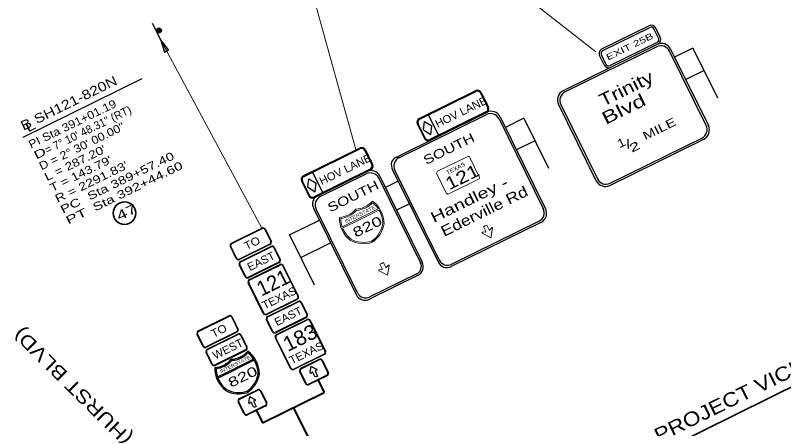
# Model space of a CAD drawing. Extents: x 2356431 to 2371438, y 6972864 to 6982525.
# Drawn here: x 2366973 to 2368116, y 6979508 to 6980123 of the extents above; entities that cross this region are included whole.
import ezdxf
from ezdxf.enums import TextEntityAlignment as Align

# ---------------------------------------------------------------- set-up
doc = ezdxf.new("R2010")
doc.units = 0
doc.header["$LTSCALE"] = 5.6
for name, color, linetype, lineweight in [('1', 7, 'Continuous', 25), ('13', 7, 'Continuous', 13), ('17', 7, 'Continuous', 35), ('28', 7, 'Continuous', 35), ('48', 7, 'Continuous', 25), ('53', 7, 'Continuous', 13), ('61', 7, 'Continuous', 13)]:
    doc.layers.add(name, color=color, linetype=linetype, lineweight=lineweight)
doc.layers.add('33', color=7, linetype='Continuous')

msp = doc.modelspace()

# ---------------------------------------------------------------- hatches: boundary and pattern name
at = {"layer": '1'}
for points in [[(2367190.135, 6980100.144, 1), (2367182.759, 6980101.279, 1)], [(2367188.543, 6980086.99), (2367194.613, 6980068.425), (2367200.923, 6980071.868)]]:
    msp.add_hatch(color=256, dxfattribs=at).paths.add_polyline_path(points)

# ---------------------------------------------------------------- linework, layer by layer
at = {"layer": '1', "lineweight": 13}
for p, q in [((2367297.678, 6980492.815), (2367836.822, 6980068.714)), ((2367347.891, 6980400.061), (2367480.094, 6979921.582)), ((2367188.543, 6980086.99), (2367339.735, 6979806.183)), ((2367645.503, 6979912.706), (2367601.335, 6979890.923)), ((2367663.388, 6979882.78), (2367649.264, 6979911.424)), ((2367600.061, 6979887.155), (2367614.185, 6979858.509)), ((2367617.952, 6979857.236), (2367662.114, 6979879.013)), ((2367512.971, 6979834.789), (2367486.067, 6979821.516)), ((2367513.98, 6979833.174), (2367486.906, 6979819.821)), ((2367459.166, 6979808.243), (2367486.067, 6979821.516)), ((2367459.816, 6979806.452), (2367486.906, 6979819.821))]:
    msp.add_line(p, q, dxfattribs=at)
at = {"layer": '1'}
for p, q in [((2367176.471, 6980111.555), (2367188.543, 6980086.99)), ((2367845.939, 6980073.212), (2367915.89, 6980107.721)), ((2367847.18, 6980070.694), (2367917.139, 6980105.194)), ((2367930.246, 6980089.228), (2367923.418, 6980103.068)), ((2367932.767, 6980090.469), (2367925.944, 6980104.312)), ((2367929.364, 6980080.427), (2367788.124, 6980010.762)), ((2367927.599, 6980076.421), (2367791.057, 6980009.062)), ((2367928.112, 6980082.955), (2367858.154, 6980048.442)), ((2368001.048, 6979959.323), (2367946.431, 6980070.028)), ((2367948.121, 6980072.954), (2368004.4, 6979958.885)), ((2367981.43, 6980074.563), (2367954.002, 6980061.034)), ((2367981.429, 6980074.563), (2368018.097, 6980000.231)), ((2367849.355, 6980049.329), (2367842.524, 6980063.166)), ((2367851.874, 6980050.573), (2367845.052, 6980064.412)), ((2367998.02, 6980040.932), (2367970.594, 6980027.403)), ((2367837.583, 6979876.599), (2367781.31, 6979990.67)), ((2367784.666, 6979990.232), (2367839.277, 6979879.526)), ((2367539.082, 6979911.593), (2367674.314, 6979978.71)), ((2367543.756, 6979911.193), (2367673.876, 6979975.358)), ((2367692.71, 6979968.968), (2367758.66, 6979835.274)), ((2367694.403, 6979971.894), (2367762.01, 6979834.836)), ((2367729.618, 6979969.859), (2367702.19, 6979956.329)), ((2367729.617, 6979969.859), (2367766.285, 6979895.526)), ((2367858.104, 6979873.136), (2367994.652, 6979940.489)), ((2367746.208, 6979936.228), (2367718.782, 6979922.698)), ((2367857.668, 6979869.784), (2367997.577, 6979938.796)), ((2367421.791, 6979853.716), (2367497.439, 6979891.235)), ((2367426.465, 6979853.317), (2367494.798, 6979887.021)), ((2367515.32, 6979883.546), (2367578.396, 6979755.665)), ((2367534.333, 6979892.951), (2367601.929, 6979755.895)), ((2367603.622, 6979758.821), (2367537.67, 6979892.519)), ((2367513.639, 6979880.62), (2367575.88, 6979754.423)), ((2367542.653, 6979876.079), (2367523.63, 6979866.697)), ((2367559.24, 6979842.445), (2367540.22, 6979833.063)), ((2367417.041, 6979835.073), (2367480.12, 6979707.171)), ((2367481.811, 6979710.097), (2367420.38, 6979834.643)), ((2367381.034, 6979796.36), (2367425.353, 6979818.222)), ((2367755.195, 6979814.747), (2367621.738, 6979748.944)), ((2367752.269, 6979816.442), (2367622.456, 6979752.43)), ((2367381.034, 6979796.36), (2367417.7, 6979722.026)), ((2367397.623, 6979762.729), (2367441.94, 6979784.587)), ((2367571.578, 6979735.577), (2367499.926, 6979700.232)), ((2367570.576, 6979738.213), (2367500.644, 6979703.719)), ((2367327.43, 6979611.196), (2367300.529, 6979597.916)), ((2367328.437, 6979609.582), (2367301.368, 6979596.223)), ((2367273.629, 6979584.639), (2367300.529, 6979597.916)), ((2367274.279, 6979582.85), (2367301.368, 6979596.223))]:
    msp.add_line(p, q, dxfattribs=at)
msp.add_lwpolyline([(2367188.543, 6980086.99), (2367194.613, 6980068.425), (2367200.923, 6980071.868)], close=True, dxfattribs=at)
msp.add_circle((2367186.447, 6980100.712), 3.732, dxfattribs=at)
for centre, radius, start, end in [((2367919.211, 6980101.011), 7.501, 26.25603, 116.25603), ((2367919.211, 6980101.011), 4.688, 26.25603, 116.25603), ((2367926.047, 6980087.154), 4.688, 296.25603, 26.25603), ((2367926.047, 6980087.154), 7.501, 296.25603, 26.25603), ((2367933.829, 6980063.807), 14.063, 26.25603, 116.25603), ((2367934.681, 6980066.318), 15.001, 26.25603, 116.25603), ((2367849.253, 6980066.502), 7.501, 116.25603, 206.25603), ((2367849.253, 6980066.502), 4.688, 116.25603, 206.25603), ((2367856.088, 6980052.645), 7.501, 206.25603, 296.25603), ((2367856.088, 6980052.645), 4.688, 206.25603, 296.25603), ((2367794.77, 6979997.304), 15.001, 116.25603, 206.25603), ((2367797.281, 6979996.452), 14.063, 116.25603, 206.25603), ((2367680.098, 6979962.747), 14.063, 26.25695, 116.25695), ((2367680.95, 6979965.258), 15.001, 26.25695, 116.25695), ((2367988.436, 6979953.103), 14.063, 296.25603, 26.25603), ((2367990.948, 6979952.251), 15.001, 296.25603, 26.25603), ((2367550.285, 6979898.737), 14.063, 116.25695, 206.25695), ((2367501.027, 6979874.396), 14.063, 26.25695, 116.25695), ((2367501.879, 6979876.907), 15.001, 26.25695, 116.25695), ((2367851.037, 6979883.236), 15.001, 206.25603, 296.25603), ((2367851.889, 6979885.747), 14.063, 206.25603, 296.25603), ((2367432.993, 6979840.86), 14.063, 116.25695, 206.25695), ((2367746.048, 6979829.053), 14.063, 296.25695, 26.25695), ((2367748.56, 6979828.201), 15.001, 296.25695, 26.25695), ((2367678.47, 6979804.117), 0.506, 206.25516, 316.23827), ((2367672.476, 6979801.161), 0.506, 276.27206, 26.25516), ((2367616.235, 6979765.042), 14.063, 206.25695, 296.25695), ((2367518.505, 6979745.223), 0.506, 276.27206, 26.25516), ((2367524.498, 6979748.179), 0.506, 206.25516, 316.23827), ((2367564.944, 6979749.029), 12.195, 296.25606, 26.25398), ((2367564.944, 6979749.029), 15, 296.25606, 26.25398), ((2367615.383, 6979762.531), 15.001, 206.25695, 296.25695), ((2367493.571, 6979713.819), 15.001, 206.25695, 296.25695), ((2367494.423, 6979716.33), 14.063, 206.25695, 296.25695), ((2367291.938, 6979646.838), 35.984, 273.44817, 318.29849), ((2367291.938, 6979646.838), 37.874, 274.64609, 315.64292), ((2367294.046, 6979589.03), 41.954, 0.13097, 53.83335), ((2367294.046, 6979589.03), 40.064, 33.57742, 51.44217), ((2367266.909, 6979634.485), 35.984, 274.23709, 319.0874), ((2367266.909, 6979634.485), 37.874, 276.89265, 317.88949), ((2367294.046, 6979589.03), 40.064, 0.34751, 30.85949), ((2367311.511, 6979597.649), 41.954, 178.70222, 232.4046), ((2367311.511, 6979597.649), 40.064, 181.0934, 198.95816), ((2367295.806, 6979595.51), 38.808, 304.10583, 350.75221), ((2367295.806, 6979595.51), 40.698, 303.73968, 350.97558), ((2367311.511, 6979597.649), 40.064, 201.67608, 232.18806), ((2367305.297, 6979600.194), 40.698, 241.55999, 288.79589), ((2367305.297, 6979600.194), 38.808, 241.78337, 288.42975)]:
    msp.add_arc(centre, radius, start, end, dxfattribs=at)
at = {"layer": '1', "lineweight": 13}
for centre, radius, start, end in [((2367646.743, 6979910.179), 2.813, 26.25588, 116.25588), ((2367602.583, 6979888.396), 2.813, 116.25588, 206.25588), ((2367660.869, 6979881.541), 2.813, 296.25588, 26.25588), ((2367616.71, 6979859.758), 2.813, 206.25588, 296.25588), ((2367477.488, 6979870.438), 35.984, 273.43645, 318.28676), ((2367477.488, 6979870.438), 37.874, 274.63436, 315.6312), ((2367479.584, 6979812.63), 41.954, 0.11925, 53.82162), ((2367479.584, 6979812.63), 40.064, 33.56569, 51.43044), ((2367452.456, 6979858.091), 35.984, 274.22536, 319.07567), ((2367452.456, 6979858.091), 37.874, 276.88092, 317.87776), ((2367479.584, 6979812.63), 40.064, 0.33578, 30.84777), ((2367497.05, 6979821.246), 41.954, 178.6905, 232.39288), ((2367497.05, 6979821.246), 40.064, 181.08168, 198.94643), ((2367497.05, 6979821.246), 40.064, 201.66436, 232.17634), ((2367481.345, 6979819.109), 38.808, 304.0941, 350.74048), ((2367481.345, 6979819.109), 40.698, 303.72796, 350.96386), ((2367490.838, 6979823.791), 40.698, 241.54826, 288.78416), ((2367490.838, 6979823.791), 38.808, 241.77164, 288.41802)]:
    msp.add_arc(centre, radius, start, end, dxfattribs=at)
at = {"layer": '1'}
for centre in [(2367546.174, 6979898.277), (2367428.883, 6979840.401)]:
    msp.add_ellipse(centre, major_axis=(-9.412, 11.91), ratio=0.848877, start_param=6.07270093, end_param=7.64349725, dxfattribs=at)
at = {"layer": '17'}
msp.add_line((2367561.881, 6979290.19), (2368209.441, 6979609.782), dxfattribs=at)
msp.add_circle((2367135.069, 6979828.531), 16.828, dxfattribs=at)
at = {"layer": '48'}
for p, q in [((2367573.76, 6979969.338), (2367658.355, 6980011.063)), ((2367574.911, 6979968.677), (2367658.176, 6980009.753)), ((2367666.266, 6980008.381), (2367676.999, 6979986.622)), ((2367675.681, 6979986.796), (2367665.6, 6980007.232)), ((2367587.464, 6979974.869), (2367602.447, 6979944.493)), ((2367674.314, 6979978.71), (2367589.721, 6979936.978)), ((2367673.158, 6979979.376), (2367589.893, 6979938.3)), ((2367580.483, 6979952.441), (2367581.921, 6979965.109)), ((2367581.921, 6979965.109), (2367592.848, 6979958.541)), ((2367571.076, 6979961.426), (2367581.868, 6979939.548)), ((2367572.397, 6979961.253), (2367582.476, 6979940.816)), ((2367580.483, 6979952.441), (2367591.411, 6979945.874)), ((2367591.411, 6979945.874), (2367592.848, 6979958.541)), ((2367401.358, 6979883.971), (2367485.954, 6979925.695)), ((2367402.507, 6979883.308), (2367485.773, 6979924.383)), ((2367503.279, 6979901.427), (2367493.198, 6979921.863)), ((2367493.864, 6979923.012), (2367504.597, 6979901.253)), ((2367500.756, 6979894.007), (2367417.49, 6979852.932)), ((2367415.061, 6979889.501), (2367430.045, 6979859.125)), ((2367501.911, 6979893.342), (2367417.319, 6979851.609)), ((2367398.674, 6979876.058), (2367409.466, 6979854.179)), ((2367399.995, 6979875.884), (2367410.074, 6979855.447)), ((2367408.082, 6979867.073), (2367409.52, 6979879.74)), ((2367409.52, 6979879.74), (2367420.447, 6979873.173)), ((2367419.009, 6979860.505), (2367420.447, 6979873.173)), ((2367408.082, 6979867.073), (2367419.009, 6979860.505)), ((2367294.5, 6979783.858), (2367339.735, 6979806.183)), ((2367294.839, 6979783.169), (2367340.074, 6979805.494)), ((2367344.189, 6979804.099), (2367352.825, 6979786.6)), ((2367344.877, 6979804.439), (2367353.514, 6979786.94)), ((2367302.08, 6979761.556), (2367293.444, 6979779.055)), ((2367351.43, 6979782.486), (2367306.195, 6979760.161)), ((2367351.77, 6979781.797), (2367306.535, 6979759.472)), ((2367307.862, 6979756.782), (2367353.097, 6979779.107)), ((2367301.392, 6979761.216), (2367292.756, 6979778.715)), ((2367308.202, 6979756.094), (2367353.437, 6979778.419)), ((2367357.551, 6979777.023), (2367366.188, 6979759.525)), ((2367358.24, 6979777.363), (2367366.876, 6979759.865)), ((2367314.754, 6979734.141), (2367306.118, 6979751.639)), ((2367315.443, 6979734.481), (2367306.807, 6979751.979)), ((2367364.792, 6979755.411), (2367319.557, 6979733.086)), ((2367365.132, 6979754.722), (2367319.897, 6979732.397)), ((2367321.225, 6979729.707), (2367366.46, 6979752.032)), ((2367321.565, 6979729.018), (2367366.8, 6979751.343)), ((2367370.914, 6979749.948), (2367393.239, 6979704.713)), ((2367371.603, 6979750.288), (2367393.928, 6979705.053)), ((2367341.806, 6979679.329), (2367319.481, 6979724.564)), ((2367342.495, 6979679.669), (2367320.17, 6979724.904)), ((2367391.844, 6979700.598), (2367346.609, 6979678.273)), ((2367392.184, 6979699.91), (2367346.949, 6979677.585)), ((2367348.277, 6979674.895), (2367393.512, 6979697.22)), ((2367348.616, 6979674.206), (2367393.851, 6979696.531)), ((2367397.966, 6979695.136), (2367406.602, 6979677.637)), ((2367398.655, 6979695.476), (2367407.291, 6979677.977)), ((2367245.096, 6979653.226), (2367290.331, 6979675.551)), ((2367245.436, 6979652.537), (2367290.671, 6979674.862)), ((2367294.785, 6979673.467), (2367303.421, 6979655.968)), ((2367295.474, 6979673.807), (2367304.11, 6979656.308)), ((2367355.169, 6979652.253), (2367346.533, 6979669.752)), ((2367355.857, 6979652.593), (2367347.221, 6979670.092)), ((2367405.207, 6979673.523), (2367359.972, 6979651.198)), ((2367405.547, 6979672.834), (2367360.312, 6979650.509)), ((2367361.639, 6979647.819), (2367406.874, 6979670.144)), ((2367361.979, 6979647.13), (2367407.214, 6979669.455)), ((2367411.329, 6979668.06), (2367433.654, 6979622.825)), ((2367412.017, 6979668.4), (2367434.342, 6979623.165)), ((2367251.988, 6979630.584), (2367243.352, 6979648.083)), ((2367252.677, 6979630.924), (2367244.041, 6979648.423)), ((2367302.026, 6979651.854), (2367256.791, 6979629.529)), ((2367302.366, 6979651.165), (2367257.131, 6979628.84)), ((2367258.459, 6979626.15), (2367303.694, 6979648.475)), ((2367258.798, 6979625.461), (2367304.034, 6979647.786)), ((2367308.148, 6979646.391), (2367316.784, 6979628.893)), ((2367308.837, 6979646.731), (2367317.473, 6979629.233)), ((2367382.22, 6979597.441), (2367359.895, 6979642.676)), ((2367382.909, 6979597.781), (2367360.584, 6979643.016)), ((2367265.351, 6979603.509), (2367256.715, 6979621.007)), ((2367266.039, 6979603.849), (2367257.403, 6979621.347)), ((2367315.389, 6979624.778), (2367270.154, 6979602.453)), ((2367315.729, 6979624.09), (2367270.494, 6979601.765)), ((2367432.258, 6979618.711), (2367387.023, 6979596.386)), ((2367432.598, 6979618.022), (2367387.363, 6979595.697)), ((2367397.909, 6979597.556), (2367424.708, 6979610.783)), ((2367398.249, 6979596.867), (2367425.048, 6979610.094)), ((2367429.162, 6979608.699), (2367437.798, 6979591.2)), ((2367429.851, 6979609.039), (2367438.487, 6979591.54)), ((2367404.801, 6979574.915), (2367396.165, 6979592.413)), ((2367405.489, 6979575.255), (2367396.853, 6979592.753)), ((2367436.403, 6979587.086), (2367409.604, 6979573.859)), ((2367436.743, 6979586.397), (2367409.944, 6979573.171)), ((2367306.338, 6979552.363), (2367333.137, 6979565.589)), ((2367306.678, 6979551.674), (2367333.477, 6979564.901)), ((2367337.592, 6979563.505), (2367346.228, 6979546.007)), ((2367338.28, 6979563.845), (2367346.916, 6979546.347)), ((2367313.23, 6979529.722), (2367304.594, 6979547.22)), ((2367313.919, 6979530.061), (2367305.283, 6979547.56)), ((2367344.833, 6979541.893), (2367318.033, 6979528.666)), ((2367345.172, 6979541.204), (2367318.373, 6979527.978))]:
    msp.add_line(p, q, dxfattribs=at)
at = {"layer": '48', "lineweight": 40}
for p, q in [((2367423.343, 6979579.784), (2367432.444, 6979561.345)), ((2367340.873, 6979516.152), (2367432.444, 6979561.345)), ((2367331.773, 6979534.591), (2367340.873, 6979516.152)), ((2367386.658, 6979538.749), (2367411.927, 6979487.55))]:
    msp.add_line(p, q, dxfattribs=at)
at = {"layer": '48'}
for points in [[(2367411.777, 6979591.018), (2367413.231, 6979600.436), (2367421.526, 6979595.911)], [(2367421.32, 6979594.485), (2367418.8, 6979593.951), (2367422.716, 6979586.013), (2367419.091, 6979584.223), (2367415.174, 6979592.161), (2367413.04, 6979590.304)], [(2367320.206, 6979545.826), (2367321.661, 6979555.243), (2367329.956, 6979550.719)], [(2367329.751, 6979549.293), (2367327.23, 6979548.758), (2367331.147, 6979540.822), (2367327.52, 6979539.031), (2367323.604, 6979546.968), (2367321.47, 6979545.112)]]:
    msp.add_lwpolyline(points, dxfattribs=at)
for centre, radius, start, end in [((2367660.633, 6980004.777), 5.54, 26.25314, 116.25314), ((2367660.969, 6980005.766), 5.909, 26.25314, 116.25314), ((2367670.709, 6979984.344), 5.54, 296.25314, 26.25314), ((2367671.698, 6979984.008), 5.909, 296.25314, 26.25314), ((2367576.375, 6979964.04), 5.909, 116.25256, 206.25256), ((2367577.364, 6979963.704), 5.54, 116.25256, 206.25256), ((2367587.108, 6979942.278), 5.909, 206.25256, 296.25256), ((2367587.444, 6979943.267), 5.54, 206.25256, 296.25256), ((2367488.231, 6979919.408), 5.54, 26.25314, 116.25314), ((2367488.567, 6979920.397), 5.909, 26.25314, 116.25314), ((2367498.307, 6979898.975), 5.54, 296.25314, 26.25314), ((2367499.296, 6979898.639), 5.909, 296.25314, 26.25314), ((2367403.973, 6979878.671), 5.909, 116.25256, 206.25256), ((2367404.962, 6979878.335), 5.54, 116.25256, 206.25256), ((2367414.707, 6979856.909), 5.909, 206.25256, 296.25256), ((2367415.042, 6979857.898), 5.54, 206.25256, 296.25256), ((2367341.434, 6979802.739), 3.84, 26.26788, 116.26788), ((2367341.434, 6979802.739), 3.072, 26.26788, 116.26788), ((2367296.199, 6979780.414), 3.84, 116.26788, 206.26788), ((2367296.199, 6979780.414), 3.072, 116.26788, 206.26788), ((2367350.07, 6979785.241), 3.072, 296.26788, 26.26788), ((2367350.07, 6979785.241), 3.84, 296.26788, 26.26788), ((2367354.797, 6979775.664), 3.84, 26.26788, 116.26788), ((2367354.797, 6979775.664), 3.072, 26.26788, 116.26788), ((2367304.835, 6979762.916), 3.84, 206.26788, 296.26788), ((2367304.835, 6979762.916), 3.072, 206.26788, 296.26788), ((2367309.562, 6979753.339), 3.84, 116.26788, 206.26788), ((2367363.433, 6979758.165), 3.072, 296.26788, 26.26788), ((2367363.433, 6979758.165), 3.84, 296.26788, 26.26788), ((2367309.562, 6979753.339), 3.072, 116.26788, 206.26788), ((2367368.159, 6979748.588), 3.84, 26.26788, 116.26788), ((2367368.159, 6979748.588), 3.072, 26.26788, 116.26788), ((2367318.198, 6979735.84), 3.84, 206.26788, 296.26788), ((2367318.198, 6979735.84), 3.072, 206.26788, 296.26788), ((2367322.924, 6979726.263), 3.84, 116.26788, 206.26788), ((2367322.924, 6979726.263), 3.072, 116.26788, 206.26788), ((2367390.484, 6979703.353), 3.072, 296.26788, 26.26788), ((2367390.484, 6979703.353), 3.84, 296.26788, 26.26788), ((2367395.211, 6979693.776), 3.84, 26.26788, 116.26788), ((2367395.211, 6979693.776), 3.072, 26.26788, 116.26788), ((2367345.249, 6979681.028), 3.84, 206.26788, 296.26788), ((2367345.249, 6979681.028), 3.072, 206.26788, 296.26788), ((2367403.847, 6979676.278), 3.072, 296.26788, 26.26788), ((2367403.847, 6979676.278), 3.84, 296.26788, 26.26788), ((2367292.03, 6979672.107), 3.84, 26.26788, 116.26788), ((2367292.03, 6979672.107), 3.072, 26.26788, 116.26788), ((2367349.976, 6979671.451), 3.84, 116.26788, 206.26788), ((2367349.976, 6979671.451), 3.072, 116.26788, 206.26788), ((2367408.574, 6979666.701), 3.84, 26.26788, 116.26788), ((2367408.574, 6979666.701), 3.072, 26.26788, 116.26788), ((2367246.795, 6979649.782), 3.84, 116.26788, 206.26788), ((2367300.666, 6979654.609), 3.072, 296.26788, 26.26788), ((2367300.666, 6979654.609), 3.84, 296.26788, 26.26788), ((2367246.795, 6979649.782), 3.072, 116.26788, 206.26788), ((2367305.393, 6979645.032), 3.84, 26.26788, 116.26788), ((2367305.393, 6979645.032), 3.072, 26.26788, 116.26788), ((2367358.612, 6979653.953), 3.84, 206.26788, 296.26788), ((2367358.612, 6979653.953), 3.072, 206.26788, 296.26788), ((2367363.339, 6979644.376), 3.84, 116.26788, 206.26788), ((2367363.339, 6979644.376), 3.072, 116.26788, 206.26788), ((2367255.431, 6979632.284), 3.84, 206.26788, 296.26788), ((2367255.431, 6979632.284), 3.072, 206.26788, 296.26788), ((2367260.158, 6979622.707), 3.84, 116.26788, 206.26788), ((2367260.158, 6979622.707), 3.072, 116.26788, 206.26788), ((2367314.029, 6979627.533), 3.072, 296.26788, 26.26788), ((2367314.029, 6979627.533), 3.84, 296.26788, 26.26788), ((2367430.899, 6979621.465), 3.072, 296.26788, 26.26788), ((2367430.899, 6979621.465), 3.84, 296.26788, 26.26788), ((2367426.408, 6979607.339), 3.84, 26.26788, 116.26788), ((2367426.408, 6979607.339), 3.072, 26.26788, 116.26788), ((2367268.794, 6979605.208), 3.84, 206.26788, 296.26788), ((2367268.794, 6979605.208), 3.072, 206.26788, 296.26788), ((2367385.664, 6979599.14), 3.84, 206.26788, 296.26788), ((2367385.664, 6979599.14), 3.072, 206.26788, 296.26788), ((2367399.608, 6979594.113), 3.84, 116.26788, 206.26788), ((2367399.608, 6979594.113), 3.072, 116.26788, 206.26788), ((2367412.533, 6979590.893), 0.767, 171.25336, 310.98193), ((2367421.159, 6979595.237), 0.767, 281.76638, 61.40499), ((2367435.044, 6979589.841), 3.072, 296.26788, 26.26788), ((2367435.044, 6979589.841), 3.84, 296.26788, 26.26788), ((2367408.244, 6979576.614), 3.84, 206.26788, 296.26788), ((2367408.244, 6979576.614), 3.072, 206.26788, 296.26788), ((2367334.837, 6979562.146), 3.84, 26.26788, 116.26788), ((2367334.837, 6979562.146), 3.072, 26.26788, 116.26788), ((2367308.038, 6979548.919), 3.84, 116.26788, 206.26788), ((2367308.038, 6979548.919), 3.072, 116.26788, 206.26788), ((2367329.589, 6979550.043), 0.767, 281.76638, 61.40499), ((2367320.962, 6979545.7), 0.767, 171.25336, 310.98193), ((2367343.473, 6979544.647), 3.072, 296.26788, 26.26788), ((2367343.473, 6979544.647), 3.84, 296.26788, 26.26788), ((2367316.674, 6979531.421), 3.84, 206.26788, 296.26788), ((2367316.674, 6979531.421), 3.072, 206.26788, 296.26788)]:
    msp.add_arc(centre, radius, start, end, dxfattribs=at)
at = {"layer": '53'}
for p, q in [((2367674.562, 6979810.877), (2367678.002, 6979803.907)), ((2367678.841, 6979803.779), (2367681.7, 6979806.77)), ((2367668.4, 6979800.206), (2367672.531, 6979800.678)), ((2367514.428, 6979744.268), (2367518.56, 6979744.74)), ((2367520.591, 6979754.939), (2367524.031, 6979747.969)), ((2367524.869, 6979747.841), (2367527.729, 6979750.833))]:
    msp.add_line(p, q, dxfattribs=at)
for points in [[(2367682.984, 6979806.096), (2367680.768, 6979791.902), (2367668.147, 6979798.778)], [(2367672.924, 6979801.401), (2367669.473, 6979808.38), (2367672.015, 6979809.632), (2367674.562, 6979810.877)], [(2367529.013, 6979750.159), (2367526.796, 6979735.964), (2367514.176, 6979742.839)], [(2367518.954, 6979745.463), (2367515.502, 6979752.442), (2367518.045, 6979753.694), (2367520.591, 6979754.939)]]:
    msp.add_lwpolyline(points, dxfattribs=at)
for centre, start, end in [((2367682.248, 6979806.239), 350.99366, 136.37479), ((2367668.493, 6979799.455), 96.13553, 241.51667), ((2367528.276, 6979750.302), 350.99366, 136.37479), ((2367514.522, 6979743.517), 96.13553, 241.51667)]:
    msp.add_arc(centre, 0.759, start, end, dxfattribs=at)
at = {"layer": '61', "lineweight": 25}
msp.add_line((2366984.556, 6979941.91), (2367161.513, 6980029.245), dxfattribs=at)

# ---------------------------------------------------------------- texts
at = {"layer": '1'}
for s, height, rotation, width, p in [('EXIT 25B', 9.188, 26.256, 1.45, (2367889.284, 6980072.648)), ('Trinity', 18.91, 26.256, 1.25, (2367886.138, 6980005.746)), ('Blvd', 18.9, 26.256, 1.4, (2367882.502, 6979975.251)), ('MILE', 12.54, 26.256, 1.35, (2367934.186, 6979948.639)), ('SOUTH', 13.5, 26.257, 1.3, (2367621.046, 6979918.368)), ('1', 12.54, 26.256, 1.3, (2367877.512, 6979927.797)), ('/', 12.54, 26.256, 1.7, (2367887.727, 6979925.727)), ('2', 12.54, 26.256, 1.65, (2367897.214, 6979921.978)), ('SOUTH', 13.5, 26.257, 1.3, (2367478.399, 6979847.678)), ('Handley -', 15.68, 26.256, 1.4, (2367651.979, 6979841.579)), ('Ederville Rd', 15.68, 26.256, 1.25, (2367674.271, 6979824.483))]:
    msp.add_text(s, height=height, rotation=rotation, dxfattribs=dict(at, width=width)).set_placement(p, align=Align.CENTER)
for s, height, rotation, width, p in [('TEXAS', 6, 26.256, 1.15, (2367615.97, 6979885.756)), ('121', 18.75, 26.256, 1.25, (2367618.575, 6979862.458)), ('INTERSTATE', 5.198, 26.256, 1.15, (2367464.48, 6979813.566)), ('820', 14.18, 26.256, 1.45, (2367479.27, 6979792.03)), ('INTERSTATE', 5.198, 26.268, 1.15, (2367278.942, 6979589.963)), ('820', 14.18, 26.268, 1.45, (2367293.737, 6979568.428))]:
    msp.add_text(s, height=height, rotation=rotation, dxfattribs=dict(at, width=width)).set_placement(p)
at = {"layer": '13', "width": 1.25}
msp.add_text('(HURST BLVD)', height=20, rotation=135.331, dxfattribs=at).set_placement((2367148.363, 6979495.458))
at = {"layer": '17', "width": 1.5}
msp.add_text('47', height=14, rotation=26.268, dxfattribs=at).set_placement((2367141.314, 6979823.806), align=Align.CENTER)
at = {"layer": '17', "width": 1.2}
msp.add_text('PROPERTY OWNERS IN  PROJECT VICINITY', height=21, rotation=26.268, dxfattribs=at).set_placement((2367564.429, 6979305.731))
at = {"layer": '28', "width": 1.25}
msp.add_text('B SH121-820N', height=14, rotation=26.377, dxfattribs=at).set_placement((2367055.384, 6979986.196), align=Align.CENTER)
at = {"layer": '33'}
for s, width, p in [('PI Sta 391+01.19', 1.15, (2366995.9, 6979924.599)), ('D = 2° 30\' 00.00"', 1.15, (2367011.734, 6979892.291)), ("L = 287.20'", 1.25, (2367019.651, 6979876.137)), ('D', 1.55, (2367003.817, 6979908.445)), ('Sta 389+57.40', 1.35, (2367083.497, 6979847.359)), ("T = 143.79'", 1.25, (2367027.569, 6979859.983)), ("R = 2291.83'", 1.3, (2367035.486, 6979843.829)), ('Sta 392+44.60', 1.4, (2367091.538, 6979830.953)), ('PC', 1.4, (2367043.403, 6979827.675)), ('PT', 1.6, (2367051.321, 6979811.521))]:
    msp.add_text(s, height=12, rotation=26.11, dxfattribs=dict(at, width=width)).set_placement(p)
msp.add_text('= 7° 10\' 48.31" (RT)', height=12, rotation=26.11, dxfattribs=at).set_placement((2367019.98, 6979916.366))
at = {"layer": '48'}
for s, height, rotation, width, p in [('HOV LANE', 11.82, 26.252, 1.05, (2367638.959, 6979973.961)), ('HOV LANE', 11.82, 26.252, 1.05, (2367466.557, 6979888.591)), ('TO', 11.82, 26.188, 1.1, (2367327.678, 6979778.697)), ('EAST', 11.82, 26.188, 1.05, (2367341.039, 6979751.621)), ('TEXAS', 11.82, 26.188, 1.05, (2367368.041, 6979696.91)), ('EAST', 11.82, 26.188, 1.05, (2367381.454, 6979669.733)), ('TO', 11.82, 26.188, 1.1, (2367278.273, 6979648.065)), ('183', 22.16, 26.188, 1.05, (2367401.47, 6979633.137)), ('WEST', 11.82, 26.188, 1.05, (2367291.637, 6979620.99)), ('TEXAS', 11.82, 26.188, 1.05, (2367408.456, 6979615.023))]:
    msp.add_text(s, height=height, rotation=rotation, dxfattribs=dict(at, width=width)).set_placement(p, align=Align.CENTER)
msp.add_text('121', height=22.16, rotation=26.188, dxfattribs=at).set_placement((2367361.055, 6979715.023), align=Align.CENTER)
at = {"layer": '61', "width": 1.4}
msp.add_text('L', height=14, rotation=26.268, dxfattribs=at).set_placement((2366998.046, 6979952.018), align=Align.CENTER)

doc.saveas('drawing.dxf')
